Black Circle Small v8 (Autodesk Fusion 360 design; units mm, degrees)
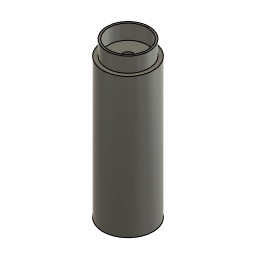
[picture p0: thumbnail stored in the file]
sketch "Sketch1" plane through (0, 0, 0) normal (0, 1, 0) x axis (1, 0, 0)
  circle C1 centre (0, 0) radius 15.25
  point P1 (0, 0)
  point P2 (0, 0)
  coincident P1 P2
  dimension "d1" diameter C1 = 30.5
extrude "Extrude1" new body sketch "Sketch1" along normal blind 85
sketch "Sketch1" plane through (0, 85, 0) normal (0, 1, 0) x axis (-1, 0, 0)
  circle C1 centre (0, 0) radius 15.25
  circle C2 centre (0, 0) radius 12.875
  circle C3 centre (0, 0) radius 11.75
  concentric C1 C2
  concentric C2 C3
  dimension "d4" diameter C2 = 25.75
  dimension "d5" diameter C3 = 23.5
hole "Hole1" HoleDepth 85 HoleDiameter 6.3 TipAngle 180
extrude "Extrude2" new body sketch "Sketch1" profile of C2 C3 along normal blind 9.1
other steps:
create_component "CreateComponent1"
create_component "CreateComponent2"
